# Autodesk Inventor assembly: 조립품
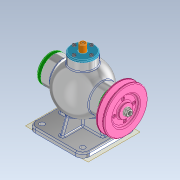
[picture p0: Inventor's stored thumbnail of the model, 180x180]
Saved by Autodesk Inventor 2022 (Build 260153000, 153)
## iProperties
Created: 2024-04
Part Number: 조립품
Document SubType Name: Assembly
Designer: admin
Author: admin
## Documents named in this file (16)
- C:\Users\admin\Desktop\740406V1008\답안조립품.iam
- C:\Users\admin\Desktop\740406V1008\본체.ipt
- C:\Users\admin\Desktop\740406V1008\뒤커버.ipt
- C:\Users\admin\Desktop\740406V1008\앞커버.ipt
- C:\Users\admin\Desktop\740406V1008\상부커버.ipt
- C:\Users\admin\Desktop\740406V1008\베어링- 6202.ipt
- KS B 2023 - 6202 - 15 x 35 x 11 - 7.8.ipt
- C:\Users\admin\Desktop\740406V1008\칼라.ipt
- C:\Users\admin\Desktop\740406V1008\편심축.ipt
- C:\Users\admin\Desktop\740406V1008\키 4 x 4 x 12.ipt
- C:\Users\admin\Desktop\740406V1008\오일실 15 30 7.ipt
- C:\Users\admin\Desktop\740406V1008\V-벨트풀리.ipt
- C:\Users\admin\Desktop\740406V1008\너트 M8.ipt
- C:\Users\admin\Desktop\740406V1008\볼트 M4 x 16.ipt
- C:\Users\admin\Desktop\740406V1008\볼트 M4 x 12.ipt
- C:\Users\admin\Desktop\740406V1008\슬라이드.ipt
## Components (15 placed, 4 different names)
1. KS B 2023 - 6202 - 15 x 35 x 11 - 7.8:1
2. KS B 2023 - 6202 - 15 x 35 x 11 - 7.8:2
3. V-벨트풀리:1
4. ISO 4762 M4 x 16:1
5. ISO 4762 M4 x 16:2
6. ISO 4762 M4 x 16:3
7. ISO 4762 M4 x 16:4
8. ISO 4762 M4 x 16:5
9. ISO 4762 M4 x 16:6
10. ISO 4762 M4 x 16:7
11. ISO 4762 M4 x 16:8
12. KS B 1021 - 에 따름 ISO 1207 - 미터 A  M 4 x 12:1
13. KS B 1021 - 에 따름 ISO 1207 - 미터 A  M 4 x 12:2
14. KS B 1021 - 에 따름 ISO 1207 - 미터 A  M 4 x 12:3
15. KS B 1021 - 에 따름 ISO 1207 - 미터 A  M 4 x 12:4
